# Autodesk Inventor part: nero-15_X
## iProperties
Shininess: 20.0
Length Units: 11269
Angle Units: 11279
Time Units: 11290
Mass Units: 11283
Length Display Precision: 2
Angle Display Precision: 2
Part Number: nero-15_X
Material: Nichtrostender Stahl - 440C
Document SubType Name: Modellieren
Description: Ipc-25 /CXX/M18
Checked By: Alves
Created: 2005-08
Designer: Ohle
Manufacturer: Standard
Standards Organization: Custom
Density: 0.0
Volumn: 0.0
Area: 0.0
PropertySet Name: Model Information
Control State: 0
Master: False
Checked Out: False
BESTELLNUMMER: Ipc-25 /CXX/M18
ME: ST
Title: Ipc Sensoren
Author: Ohle
Comments: keine Bemerkung
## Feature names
1. Grundkörper pico+ [Revolution]
2. Pole [Extrusion]
3. Rundung Pole [Fillet]
4. Verdrehsicherung [Extrusion]
5. Bohrung Ausrichtung [Extrusion]
